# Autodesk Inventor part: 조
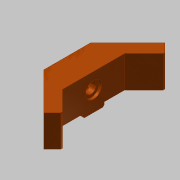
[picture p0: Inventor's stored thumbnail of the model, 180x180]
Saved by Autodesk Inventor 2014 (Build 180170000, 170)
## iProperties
Created: 2019-04
Part Number: 조
Material: 알루미늄 6061
Document SubType Name: Modeling
Designer: mduedu
Density: 1 g/cm^3
Appearance: Smooth - Light Orange
Author: mduedu
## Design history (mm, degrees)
sketch "스케치1"
  geometry: L1 (45.962, 0)-(0, -45.962); L2 (0, -45.962)-(-45.962, 0); L3 (-45.962, 0)-(0, 45.962); L4 (0, 45.962)-(45.962, 0); L5 (45.962, 0)-(-45.962, 0); L6 (0, -45.962)-(0, 45.962); 1 further point
  constraints: 12 end point, 2 midpoint, 2 parallel, 2 perpendicular, 1 horizontal
  dimensions: "d0" = 65 distance of L1.end L2.end
extrude "돌출1" new body sketch "스케치1" distance "d2" = 27; taper "d3" = 0 deg
chamfer "모따기1" distance "d4" = 25; stored, may be unused: second distance "d5" = 2, angle "d6" = 45 deg
sketch "스케치2"
  geometry: L1 (-17.678, 28.284)-(-45.962, 0) reference; L2 (-17.678, 28.284)-(17.678, 28.284) reference; L3 (45.962, 0)-(17.678, 28.284) reference; L4 (-45.962, 0)-(0, -45.962) reference; L5 (0, -45.962)-(45.962, 0) reference; L6 (-23.536, 8.284)-(23.536, 8.284); L7 (-23.536, 8.284)-(-38.891, -7.071); L8 (38.891, -7.071)-(23.536, 8.284); 1 further point
  constraints: 6 end point, 3 parallel, 2 point on line
  dimensions: "d7" = 20 distance between parallel lines of L6 L2; "d8" = 10 distance between parallel lines of L1 L7; "d9" = 10 distance between parallel lines of L3 L8
extrude "돌출2" cut sketch "스케치2" stored distance "d10" = 27; taper "d11" = 0 deg
sketch "스케치3"
  geometry: L1 (63.64, -27)-(63.64, 0) reference; L2 (56.569, -27)-(63.64, -27) reference; L3 (-28.284, -27)-(-28.284, 0) reference; L4 (-28.284, -27)-(-21.213, -27) reference; L5 (63.64, -27)-(25.678, -27); L6 (25.678, -27)-(25.678, -24); L7 (25.678, -24)-(63.64, -24); L8 (63.64, -24)-(63.64, -27); L9 (-28.284, -27)-(9.678, -27); L10 (9.678, -27)-(9.678, -24); L11 (9.678, -24)-(-28.284, -24); L12 (-28.284, -24)-(-28.284, -27); L13 (41.213, 0)-(-5.858, 0) reference; L14 (17.678, -27)-(17.678, 0)
  constraints: 18 end point, 4 parallel, 2 horizontal, 2 perpendicular, 1 midpoint, 1 symmetric about line
  dimensions: "d12" = 3 distance between parallel lines of L5 L7; "d14" = 16 distance between parallel lines of L10 L6
extrude "돌출3" cut sketch "스케치3" stored distance "d15" = 27; taper "d16" = 0 deg
sketch "스케치4"
  geometry: L1 (31.536, -27)-(15.536, -27) reference; L2 (31.536, -24)-(47.071, -24) reference; 3 further points
  constraints: 1 midpoint, 1 vertical alignment
  dimensions: "d17" = 12 distance from line of L2 point (23.536, -12)
hole "구멍1" sketch "스케치4" at (23.536, -12) diameter "d18" = 8; stored, may be unused: countersink angle "d22" = 90 deg, drill point angle "d24" = 118 deg; dims "d19" = 6, "d20" = 12.5, "d21" = 2, "d23" = 14
node "작업 평면1"
sketch "스케치5"
  geometry: L1 (0, -15)-(0, 0); L2 (-50, -4)-(50, -4); L3 (50, -4)-(50, -1.75); L4 (-50, -1.75)-(-50, -4); L5 (12, -1.75)-(12, -2.75); L6 (12, -2.75)-(-12, -2.75); L7 (-12, -2.75)-(-12, -1.75); L8 (50, -1.75)-(12, -1.75); L9 (-12, -1.75)-(-50, -1.75); C1 r 4 at (0, 0) reference; 2 further points
  constraints: 18 end point, 4 parallel, 2 midpoint, 2 vertical, 2 vertical alignment, 1 collinear, 1 horizontal, 1 perpendicular, 1 tangent
  dimensions: "d26" = 2.5 diameter of L6 L2; "d28" = 4.5 diameter of L8 L2; "d29" = 24 distance of L5.end L6.end; "d30" = 100 distance between parallel lines of L3 L4
revolve "회전1" sketch "스케치5" stored, may be unused: angle "d31" = 90 deg
chamfer "모따기2" distance "d32" = 1; stored, may be unused: second distance "d33" = 2, angle "d34" = 45 deg
chamfer "모따기3" distance "d35" = 1; stored, may be unused: second distance "d36" = 2, angle "d37" = 45 deg
node "솔리드1"
other parameters: "d25" = -5
